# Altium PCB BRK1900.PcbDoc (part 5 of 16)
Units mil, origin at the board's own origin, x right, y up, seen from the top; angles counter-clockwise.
Board outline 8858.27 x 5905.51 mil, 10 copper layers (L1-TOP, L2-GND, L3-PWR, L4-GND, L5-PWR, L6-PWR, L7-GND, L8-SIG, L9-GND, L10-BOT), stack 48.824 mil thick; 456 components, 571 nets, 2296 pads, 2416 vias.
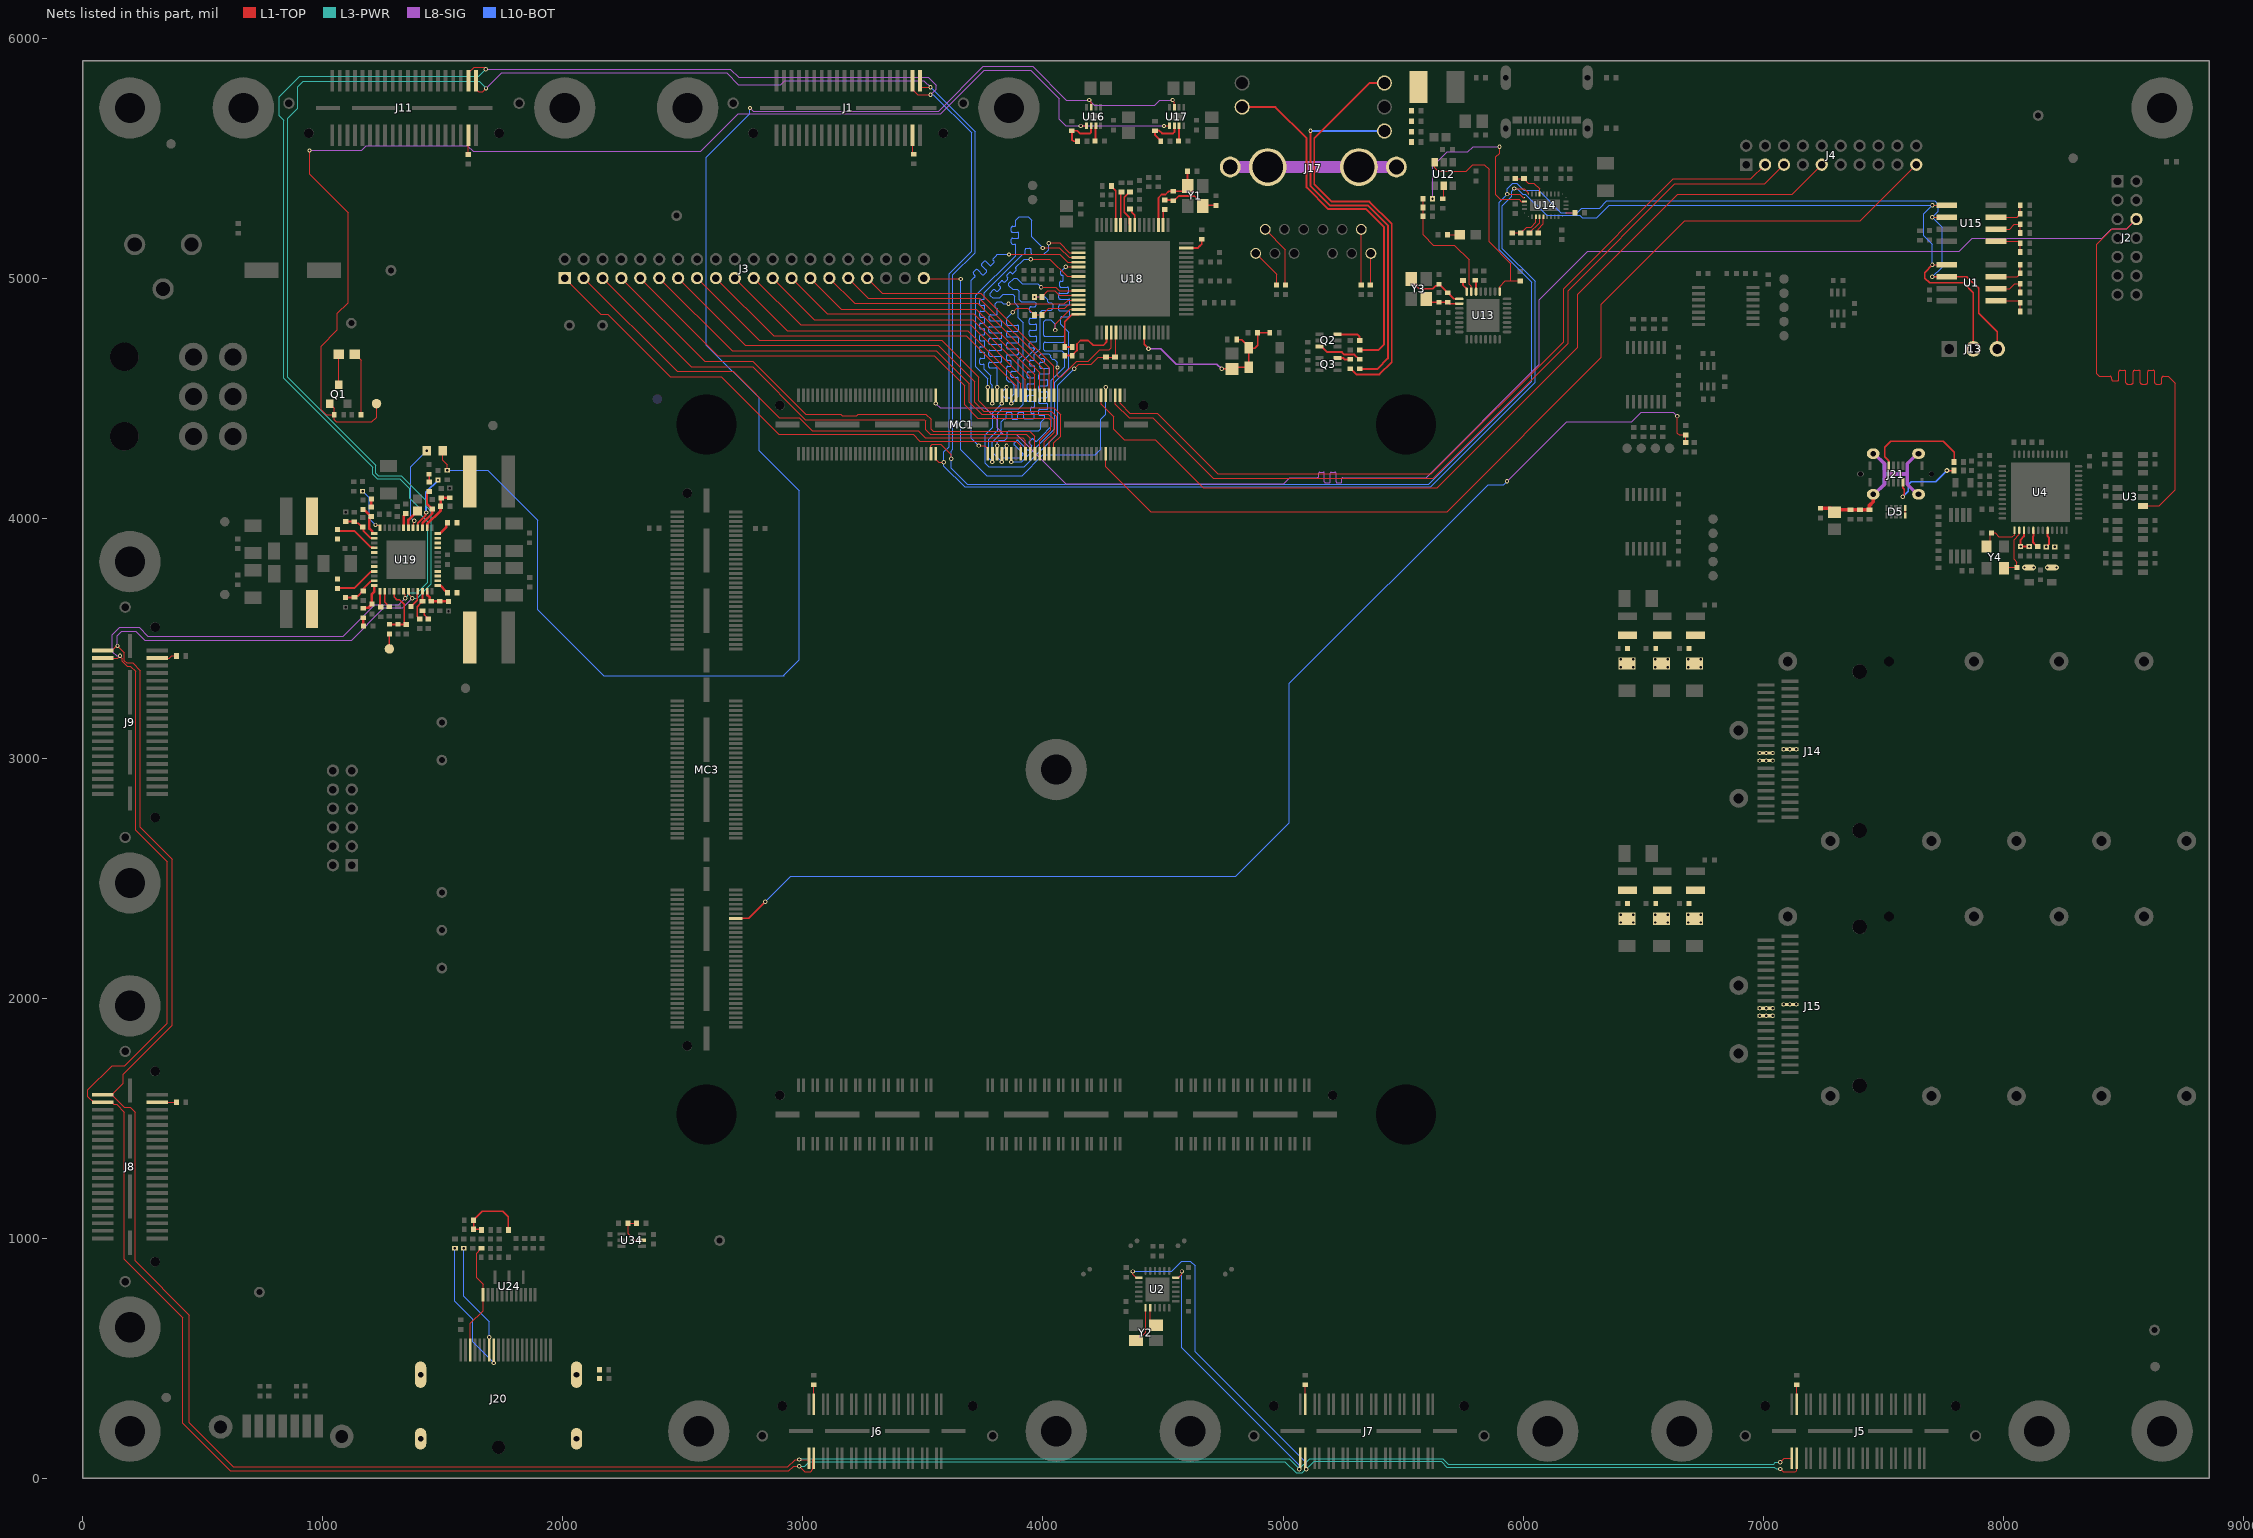
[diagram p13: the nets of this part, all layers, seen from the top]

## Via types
v1: diameter 18, hole 10, L1-TOP to L10-BOT, tented both sides, 2170 vias
v2: diameter 20, hole 10, L1-TOP to L10-BOT, tented both sides, 246 vias

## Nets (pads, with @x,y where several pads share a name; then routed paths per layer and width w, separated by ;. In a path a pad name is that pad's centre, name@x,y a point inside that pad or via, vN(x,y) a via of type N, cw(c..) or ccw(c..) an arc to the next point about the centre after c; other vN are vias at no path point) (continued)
GIGE_RX_CLK: MC1.64 U18.43 | length 1477.6
  L1-TOP w4.55: v1(3992.13,4962.11) 4053.64,4962.11 4067.68,4948.07 U18.43@4148.24,4948.07
  L10-BOT w4.55: v1(3789.37,4234.11) 3774,4249.48 3774,4329 3811.02,4366.02 3811.02,4437.01 3830.29,4456.27 3899.35,4456.27 3917.32,4474.24 3917.32,4655.08 3959.65,4697.4 3963.36,4701.11 ccw(c3959.89,4704.58) 3959.89,4709.49 3947.71,4709.49 cw(c3947.71,4714.4) 3942.8,4714.4 3942.8,4729.14 cw(c3947.71,4729.14) 3947.71,4734.05 3968.8,4734.05 ccw(c3968.8,4738.95) 3973.71,4738.95 3973.71,4753.68 ccw(c3968.8,4753.68) 3968.8,4758.59 3947.71,4758.59 cw(c3947.71,4763.5) 3942.8,4763.5 3942.8,4778.23 cw(c3947.71,4778.23) 3947.71,4783.14 3968.8,4783.14 ccw(c3968.8,4788.06) 3973.71,4788.06 3973.71,4802.78 ccw(c3968.8,4802.78) 3968.8,4807.69 3947.71,4807.69 cw(c3947.71,4812.6) 3942.8,4812.6 3942.8,4827.33 cw(c3947.71,4827.33) 3947.71,4832.24 3968.8,4832.24 ccw(c3968.8,4837.15) 3973.71,4837.15 3973.71,4851.89 ccw(c3968.8,4851.89) 3968.8,4856.8 3950.37,4856.8 cw(c3950.37,4861.7) 3945.46,4861.7 3945.46,4876.43 cw(c3950.37,4876.43) 3950.37,4881.34 3966.09,4881.34 ccw(c3966.09,4886.25) 3971,4886.25 3971,4895.14 3968.9,4897.24 3964.57,4901.57 3908.8,4901.57 3900.98,4909.39 3900.98,4944.8 3893.03,4952.76 3874.02,4952.76 3858.27,4968.5 3858.27,4978.52 3879.75,5000 3889.76,5000 3913.39,4976.38 3977.85,4976.38 v1(3992.13,4962.11)
GIGE_RX_DV: MC1.67 R95.1 R96.2 U18.53 | length 1234
  L1-TOP w4.55: v1(4129.92,4622.05) 4149.61,4641.73 4200.79,4641.73 4230.26,4671.21 R96.2@4262.72,4671.21 4262.95,4670.97 R95.1@4299.83,4670.97 4303.75,4674.89 U18.53@4303.75,4772.87
  L10-BOT w4.55: v1(3828.74,4477.42) 3791.34,4440.02 3791.34,4377.95 3759.84,4346.46 3759.84,4228.35 3774,4214.19 3922.85,4214.19 4060.73,4352.07 4060.73,4552.86 v1(4129.92,4622.05)
GIGE_RXD0: MC1.68 R62.1 R90.2 U18.44 | length 1492.4
  L1-TOP w4.55: R62.1@3964.57,4923.23 v1(3964.57,4921.26) R90.2@3996.06,4921.26 3996.06,4923.23 4019.33,4946.49 4049.57,4946.49 4067.68,4928.38 U18.44@4148.24,4928.38
  L10-BOT w4.55: v1(3828.74,4234.11) 3787.88,4274.97 3787.88,4315.88 3826.55,4354.55 3826.55,4401.35 3838.58,4413.39 3839.28,4413.39 3841.56,4413.39 ccw(c3841.56,4418.3) 3846.47,4418.3 3846.47,4435.65 cw(c3851.38,4435.65) 3851.38,4440.56 3866.11,4440.56 cw(c3866.11,4435.65) 3871.02,4435.65 3871.02,4416.88 ccw(c3875.93,4416.88) 3875.93,4411.97 3890.66,4411.97 ccw(c3890.66,4416.88) 3895.57,4416.88 3895.57,4435.65 cw(c3900.48,4435.65) 3900.48,4440.56 3915.21,4440.56 cw(c3915.21,4435.65) 3920.12,4435.65 3920.12,4418.3 ccw(c3925.03,4418.3) 3925.03,4413.39 3952.76,4413.39 3958.85,4413.39 3964.6,4419.13 3964.6,4430.37 3964.6,4432.65 ccw(c3959.69,4432.65) 3959.69,4437.56 3953.11,4437.56 cw(c3953.11,4442.47) 3948.2,4442.47 3948.2,4457.2 cw(c3953.11,4457.2) 3953.11,4462.11 3961.19,4462.11 ccw(c3961.19,4467.02) 3966.1,4467.02 3966.1,4481.75 ccw(c3961.19,4481.75) 3961.19,4486.66 3939.37,4486.66 cw(c3939.37,4491.57) 3934.46,4491.57 3934.46,4506.3 cw(c3939.37,4506.3) 3939.37,4511.21 3961.19,4511.21 ccw(c3961.19,4516.12) 3966.1,4516.12 3966.1,4530.85 ccw(c3961.19,4530.85) 3961.19,4535.76 3939.37,4535.76 cw(c3939.37,4540.67) 3934.46,4540.67 3934.46,4555.4 cw(c3939.37,4555.4) 3939.37,4560.31 3961.19,4560.31 ccw(c3961.19,4565.22) 3966.1,4565.22 3966.1,4579.95 ccw(c3961.19,4579.95) 3961.19,4584.86 3939.37,4584.86 cw(c3939.37,4589.77) 3934.46,4589.77 3934.46,4604.5 cw(c3939.37,4604.5) 3939.37,4609.41 3961.19,4609.41 ccw(c3961.19,4614.32) 3966.1,4614.32 3966.1,4629.05 ccw(c3961.19,4629.05) 3961.19,4633.96 3948.87,4633.96 cw(c3948.87,4638.87) 3943.96,4638.87 3943.96,4653.6 cw(c3948.87,4653.6) 3948.87,4658.51 3959.69,4658.51 ccw(c3959.69,4663.42) 3964.6,4663.42 3964.6,4677.17 3964.6,4681.84 3988.19,4705.43 3988.19,4858.27 3996.06,4866.14 4035.43,4866.14 4043.31,4874.02 4043.31,4889.76 4035.43,4897.64 4023.62,4897.64 4019.69,4901.57 4019.69,4909.45 4007.87,4921.26 v1(3964.57,4921.26)
GIGE_RXD1: MC1.65 U18.45 | length 1171
  L1-TOP w4.55: v1(3856.47,4892.79) 4089.49,4892.79 4105.39,4908.7 U18.45@4148.24,4908.7
  L10-BOT w4.55: v1(3809.05,4545.42) 3809.05,4618.7 3809.05,4620.98 ccw(c3804.14,4620.98) 3804.14,4625.89 3779.32,4625.89 cw(c3779.32,4630.8) 3774.41,4630.8 3774.41,4645.53 cw(c3779.32,4645.53) 3779.32,4650.44 3824.22,4650.44 ccw(c3824.22,4655.35) 3829.13,4655.35 3829.13,4670.08 ccw(c3824.22,4670.08) 3824.22,4674.99 3779.32,4674.99 cw(c3779.32,4679.9) 3774.41,4679.9 3774.41,4694.63 cw(c3779.32,4694.63) 3779.32,4699.54 3824.22,4699.54 ccw(c3824.22,4704.45) 3829.13,4704.45 3829.13,4719.18 ccw(c3824.22,4719.18) 3824.22,4724.09 3779.32,4724.09 cw(c3779.32,4729) 3774.41,4729 3774.41,4743.73 cw(c3779.32,4743.73) 3779.32,4748.64 3824.22,4748.64 ccw(c3824.22,4753.55) 3829.13,4753.55 3829.13,4768.28 ccw(c3824.22,4768.28) 3824.22,4773.19 3779.32,4773.19 cw(c3779.32,4778.1) 3774.41,4778.1 3774.41,4792.83 cw(c3779.32,4792.83) 3779.32,4797.74 3824.22,4797.74 ccw(c3824.22,4802.65) 3829.13,4802.65 3829.13,4817.38 ccw(c3824.22,4817.38) 3824.22,4822.29 3781.98,4822.29 cw(c3781.98,4827.2) 3777.07,4827.2 3777.07,4841.93 cw(c3781.98,4841.93) 3781.98,4846.84 3804.14,4846.84 ccw(c3804.14,4851.75) 3809.05,4851.75 3809.05,4869.7 3809.05,4871.83 3801.59,4879.3 3801.59,4893.51 3809.65,4901.57 3826.77,4901.57 3835.56,4892.79 v1(3856.47,4892.79)
GIGE_RXD2: MC1.69 R63.1 R91.2 U18.46 | length 1087.6
  L1-TOP w4.55: v1(3874.02,4858.27) 3889.76,4874.02 3937.01,4874.02 3955.03,4855.99 3957,4855.99 3964.57,4848.43 R63.1@3964.57,4846.46 R91.2@3996.06,4846.46 4023.62,4874.02 4090.55,4874.02 4104.89,4888.35 4147.58,4888.35 U18.46@4148.24,4889.01
  L10-BOT w4.55: v1(3848.42,4545.42) 3832,4528.99 3832,4510 3840,4502 3865,4502 3881,4518 3881,4554 3867.12,4567.88 3857.77,4567.88 3848.42,4577.23 3848.42,4582.68 3848.42,4627.25 cw(c3853.33,4627.25) 3853.33,4632.16 3862.13,4632.16 ccw(c3862.13,4637.07) 3867.04,4637.07 3867.04,4651.8 ccw(c3862.13,4651.8) 3862.13,4656.71 3852.97,4656.71 cw(c3852.97,4661.62) 3848.06,4661.62 3848.06,4676.35 cw(c3852.97,4676.35) 3852.97,4681.26 3893.51,4681.26 ccw(c3893.51,4686.17) 3898.42,4686.17 3898.42,4700.9 ccw(c3893.51,4700.9) 3893.51,4705.81 3852.97,4705.81 cw(c3852.97,4710.72) 3848.06,4710.72 3848.06,4725.45 cw(c3852.97,4725.45) 3852.97,4730.36 3893.51,4730.36 ccw(c3893.51,4735.27) 3898.42,4735.27 3898.42,4750 ccw(c3893.51,4750) 3893.51,4754.91 3852.97,4754.91 cw(c3852.97,4759.82) 3848.06,4759.82 3848.06,4774.55 cw(c3852.97,4774.55) 3852.97,4779.46 3893.51,4779.46 ccw(c3893.51,4784.37) 3898.42,4784.37 3898.42,4799.1 ccw(c3893.51,4799.1) 3893.51,4804.01 3853.33,4804.01 cw(c3853.33,4808.92) 3848.42,4808.92 3848.42,4811.2 3848.42,4832.68 v1(3874.02,4858.27)
GIGE_RXD3: MC1.70 U18.47 | length 1401.9
  L1-TOP w4.55: v1(4051.18,4783.46) 4051.18,4807.09 4113.42,4869.33 U18.47@4148.24,4869.33
  L10-BOT w4.55: v1(3848.42,4302.11) 3826.77,4280.46 3826.77,4259.84 3834.65,4251.97 3905.51,4251.97 3909.45,4255.91 3916.1,4262.56 ccw(c3912.63,4266.03) 3916.1,4269.5 3879.58,4306.02 cw(c3883.06,4309.5) 3879.58,4312.97 3890,4323.38 cw(c3893.47,4319.91) 3896.94,4323.38 3935.12,4285.21 ccw(c3938.59,4288.68) 3942.06,4285.21 3952.48,4295.62 ccw(c3949.01,4299.09) 3952.48,4302.57 3943.07,4311.98 cw(c3946.54,4315.45) 3943.07,4318.92 3953.49,4329.34 cw(c3956.96,4325.86) 3960.43,4329.34 3968.18,4321.58 ccw(c3971.65,4325.05) 3975.13,4321.58 3994.09,4340.55 4035.43,4381.89 4035.43,4574.8 4090.55,4629.92 4090.55,4685.04 4078.74,4696.85 4008.37,4696.85 4004.08,4701.14 4003.94,4701.28 4003.94,4727.97 cw(c4008.85,4727.97) 4008.85,4732.88 4086.71,4732.88 ccw(c4086.71,4737.79) 4091.62,4737.79 4091.62,4752.52 ccw(c4086.71,4752.52) 4086.71,4757.43 4008.85,4757.43 cw(c4008.85,4762.34) 4003.94,4762.34 4003.94,4799.21 4003.94,4818.9 4011.81,4826.77 4031.5,4826.77 4051.18,4807.09 v1(4051.18,4783.46)
GIGE_RXD4: R64.1 R92.2 U18.48 | length 208.2
  L1-TOP w7.5: R92.2@4122.05,4712.6 R64.1@4090.55,4712.6 4090.55,4818.9 4119.14,4847.49 4146.08,4847.49 U18.48@4148.24,4849.64
GIGE_RXD7: R104.1 R105.2 U18.51 | length 272
  L1-TOP w7.5: R104.1@4090.55,4677.17 R105.2@4122.05,4677.17 ; R105.2@4122.05,4675.2 R105.2@4122.05,4677.17 ; U18.51@4264.38,4772.87 4264.38,4732.88 4251.97,4720.47 4208.66,4720.47 4188.98,4740.16 4156.36,4740.16 4141.73,4725.53 4141.73,4698.82 4122.05,4679.13 R105.2@4122.05,4677.17
GIGE_TX_CLK: MC1.71 U18.40 | length 1180.5
  L1-TOP w4.55: v1(3948.82,5078.74) 4029.07,5078.74 4100.69,5007.12 U18.40@4148.24,5007.12
  L10-BOT w4.55: v1(3868.11,4477.42) 3897.64,4506.95 3897.64,4579.97 3897.64,4582.24 ccw(c3892.73,4582.24) 3892.73,4587.15 3871.53,4587.15 cw(c3871.53,4592.06) 3866.62,4592.06 3866.62,4606.79 cw(c3871.53,4606.79) 3871.53,4611.7 3892.73,4611.7 ccw(c3892.73,4616.61) 3897.64,4616.61 3897.64,4653.54 3897.64,4661.42 3917.32,4681.1 3917.32,4814.96 3898,4834.28 3898,4881.53 3882.16,4897.37 3882.16,4924.91 3874,4933.07 3834.95,4933.07 3819.2,4917.32 3789.82,4917.32 3780,4927.14 3780,4929.39 3780,4937.48 3793.19,4950.67 cw(c3796.66,4947.2) 3800.13,4950.67 3805.02,4945.78 ccw(c3808.49,4949.26) 3811.97,4945.78 3822.38,4956.2 ccw(c3818.91,4959.67) 3822.38,4963.14 3815.17,4970.36 cw(c3818.64,4973.83) 3815.17,4977.3 3825.58,4987.72 cw(c3829.05,4984.25) 3832.53,4987.72 3835.18,4985.06 ccw(c3838.65,4988.54) 3842.12,4985.06 3852.54,4995.48 ccw(c3849.07,4998.95) 3852.54,5002.42 3849.89,5005.08 cw(c3853.36,5008.55) 3849.89,5012.02 3860.3,5022.44 cw(c3863.77,5018.97) 3867.24,5022.44 3869.57,5020.11 ccw(c3873.05,5023.58) 3876.52,5020.11 3886.93,5030.52 ccw(c3883.46,5034) 3886.93,5037.47 cw(c3890.4,5040.94) 3886.93,5044.41 3917.32,5074.8 3921.26,5078.74 v1(3948.82,5078.74)
GIGE_TX_EN: MC1.66 U18.52 | length 1372.2
  L1-TOP w4.55: v1(4060.6,4627.48) 4059.06,4625.94 4059.06,4594.52 4064.39,4589.19 4075.46,4589.19 4140.53,4654.26 4189.14,4654.26 4235.67,4700.79 4276.05,4700.79 4284.06,4708.8 U18.52@4284.06,4772.87
  L10-BOT w4.55: v1(3809.05,4302.11) 3809.05,4316.93 3817.63,4325.5 3841.55,4325.5 3850.92,4334.87 3850.92,4358.79 3856.86,4364.73 3981.86,4364.73 3990,4372.87 3990,4399 4007.87,4416.87 4007.87,4421.61 4007.87,4423.89 ccw(c4002.96,4423.89) 4002.96,4428.8 3987.16,4428.8 cw(c3987.16,4433.71) 3982.25,4433.71 3982.25,4448.44 cw(c3987.16,4448.44) 3987.16,4453.35 4014.6,4453.35 ccw(c4014.6,4458.26) 4019.51,4458.26 4019.51,4472.99 ccw(c4014.6,4472.99) 4014.6,4477.9 3987.16,4477.9 cw(c3987.16,4482.81) 3982.25,4482.81 3982.25,4497.54 cw(c3987.16,4497.54) 3987.16,4502.45 4014.6,4502.45 ccw(c4014.6,4507.36) 4019.51,4507.36 4019.51,4522.09 ccw(c4014.6,4522.09) 4014.6,4527 3987.16,4527 cw(c3987.16,4531.91) 3982.25,4531.91 3982.25,4546.64 cw(c3987.16,4546.64) 3987.16,4551.55 4014.6,4551.55 ccw(c4014.6,4556.46) 4019.51,4556.46 4019.51,4571.19 ccw(c4014.6,4571.19) 4014.6,4576.1 3987.16,4576.1 cw(c3987.16,4581.01) 3982.25,4581.01 3982.25,4595.74 cw(c3987.16,4595.74) 3987.16,4600.65 4022.96,4600.65 ccw(c4022.96,4605.56) 4027.87,4605.56 4027.87,4620.29 ccw(c4022.96,4620.29) 4022.96,4625.2 3990.97,4625.2 cw(c3990.97,4630.11) 3986.06,4630.11 3986.06,4644.84 cw(c3990.97,4644.84) 3990.97,4649.75 4002.96,4649.75 ccw(c4002.96,4654.66) 4007.87,4654.66 4007.87,4659.39 4002.09,4665.17 4000.18,4667.08 3988.37,4667.08 3984.25,4671.2 3984.25,4677.17 3992.13,4685.04 4023.62,4685.04 4031.5,4677.17 4031.5,4669.29 4039.37,4661.42 4047.24,4661.42 4058.83,4649.83 4058.83,4629.26 v1(4060.6,4627.48)
GIGE_TXD0: MC1.72 U18.38 | length 1260.6
  L1-TOP w4.55: v1(4094.49,5047.24) 4094.86,5046.87 4147.86,5046.87 U18.38@4148.24,5046.49
  L10-BOT w4.55: v1(3868.11,4234.11) 3911.28,4234.11 4049.01,4371.84 4049.01,4565.84 4108.28,4625.11 4108.28,4773.61 4074.8,4807.09 4074.8,4807.5 4074.8,4834.32 cw(c4079.71,4834.32) 4079.71,4839.23 4106.88,4839.23 ccw(c4106.88,4844.14) 4111.79,4844.14 4111.79,4858.87 ccw(c4106.88,4858.87) 4106.88,4863.78 4069.93,4863.78 cw(c4069.93,4868.69) 4065.02,4868.69 4065.02,4883.42 cw(c4069.93,4883.42) 4069.93,4888.33 4106.88,4888.33 ccw(c4106.88,4893.24) 4111.79,4893.24 4111.79,4907.97 ccw(c4106.88,4907.97) 4106.88,4912.88 4069.93,4912.88 cw(c4069.93,4917.79) 4065.02,4917.79 4065.02,4932.52 cw(c4069.93,4932.52) 4069.93,4937.43 4101.79,4937.43 ccw(c4101.79,4942.34) 4106.7,4942.34 4106.7,4957.07 ccw(c4101.79,4957.07) 4101.79,4961.98 4074.8,4961.98 cw(c4074.8,4966.89) 4069.89,4966.89 4069.89,4981.62 cw(c4074.8,4981.62) 4074.8,4986.53 4079.71,4986.53 ccw(c4079.71,4991.44) 4084.62,4991.44 4084.62,5006.17 ccw(c4079.71,5006.17) 4079.71,5011.08 cw(c4079.71,5015.99) 4074.8,5015.99 4074.8,5027.56 4082.98,5035.74 v1(4094.49,5047.24)
GIGE_TXD1: MC1.62 U18.37 | length 1386.4
  L1-TOP w4.55: v1(3733.02,4302.37) 3756.63,4302.37 3769.68,4289.32 MC1.62@3769.68,4268.11 ; v1(3858.27,5098.43) 4070.87,5098.43 4103.12,5066.18 U18.37@4148.24,5066.18
  L10-BOT w4.55: v1(3733.02,4302.37) 3702,4333.38 3702,4990.1 3714.41,5002.51 3716.02,5004.12 ccw(c3712.55,5007.59) 3716.02,5011.06 3710.02,5017.06 cw(c3713.49,5020.53) 3710.02,5024 3720.44,5034.42 cw(c3723.91,5030.95) 3727.38,5034.42 3746.94,5014.86 ccw(c3750.41,5018.33) 3753.89,5014.86 3764.3,5025.27 ccw(c3760.83,5028.75) 3764.3,5032.22 3744.74,5051.78 cw(c3748.21,5055.25) 3744.74,5058.72 3755.16,5069.14 cw(c3758.63,5065.67) 3762.1,5069.14 3777.86,5053.38 ccw(c3781.33,5056.85) 3784.8,5053.38 3795.22,5063.79 ccw(c3791.75,5067.27) 3795.22,5070.74 3792.4,5073.56 cw(c3795.87,5077.03) 3792.4,5080.5 3805.58,5093.68 3810.32,5098.43 v1(3858.27,5098.43)
GIGE_TXD2: MC1.61 U18.36 | length 1244.8
  L1-TOP w4.55: v1(3998.51,5125.51) 4068.83,5125.51 4108.48,5085.86 U18.36@4148.24,5085.86
  L10-BOT w4.55: v1(3769.68,4545.42) 3769.68,4580.71 3720.47,4629.92 3720.47,4927.83 3886.48,5093.84 3886.48,5134.11 3886.48,5136.39 ccw(c3881.57,5136.39) 3881.57,5141.3 3873.49,5141.3 cw(c3873.49,5146.21) 3868.58,5146.21 3868.58,5160.94 cw(c3873.49,5160.94) 3873.49,5165.85 3894.56,5165.85 ccw(c3894.56,5170.76) 3899.47,5170.76 3899.47,5185.49 ccw(c3894.56,5185.49) 3894.56,5190.4 3873.49,5190.4 cw(c3873.49,5195.31) 3868.58,5195.31 3868.58,5210.04 cw(c3873.49,5210.04) 3873.49,5214.95 3881.57,5214.95 ccw(c3881.57,5219.86) 3886.48,5219.86 3886.48,5228.35 3886.48,5241.11 3901.1,5255.73 3938.46,5255.73 3952.76,5241.43 3952.76,5171.27 v1(3998.51,5125.51)
GIGE_TXD3: MC1.63 U18.35 | length 1240.2
  L1-TOP w4.55: v1(4024.53,5145.1) 4026.36,5146.94 4069.6,5146.94 4110.47,5106.06 4147.72,5106.06 U18.35@4148.24,5105.55
  L10-BOT w4.55: v1(3789.37,4477.42) 3789.37,4553.15 3783.46,4559.06 3783.46,4592.46 3755.91,4620.01 3755.91,4633.86 3755.91,4636.14 ccw(c3751,4636.14) 3751,4641.05 3740.82,4641.05 cw(c3740.82,4645.96) 3735.91,4645.96 3735.91,4660.69 cw(c3740.82,4660.69) 3740.82,4665.6 3753.36,4665.6 ccw(c3753.36,4670.51) 3758.27,4670.51 3758.27,4685.24 ccw(c3753.36,4685.24) 3753.36,4690.15 3740.82,4690.15 cw(c3740.82,4695.06) 3735.91,4695.06 3735.91,4709.79 cw(c3740.82,4709.79) 3740.82,4714.7 3753.36,4714.7 ccw(c3753.36,4719.61) 3758.27,4719.61 3758.27,4734.34 ccw(c3753.36,4734.34) 3753.36,4739.25 3740.82,4739.25 cw(c3740.82,4744.16) 3735.91,4744.16 3735.91,4758.89 cw(c3740.82,4758.89) 3740.82,4763.8 3753.36,4763.8 ccw(c3753.36,4768.71) 3758.27,4768.71 3758.27,4783.44 ccw(c3753.36,4783.44) 3753.36,4788.35 3740.82,4788.35 cw(c3740.82,4793.26) 3735.91,4793.26 3735.91,4807.99 cw(c3740.82,4807.99) 3740.82,4812.9 3753.36,4812.9 ccw(c3753.36,4817.81) 3758.27,4817.81 3758.27,4832.54 ccw(c3753.36,4832.54) 3753.36,4837.45 3740.82,4837.45 cw(c3740.82,4842.36) 3735.91,4842.36 3735.91,4857.09 cw(c3740.82,4857.09) 3740.82,4862 3753.36,4862 ccw(c3753.36,4866.91) 3758.27,4866.91 3758.27,4881.64 ccw(c3753.36,4881.64) 3753.36,4886.55 3740.82,4886.55 cw(c3740.82,4891.46) 3735.91,4891.46 3735.91,4906.19 cw(c3740.82,4906.19) 3740.82,4911.1 3751,4911.1 ccw(c3751,4916.01) 3755.91,4916.01 3755.91,4933.23 3755.91,4938.15 3916.18,5098.43 3918.46,5098.43 3920.73,5098.43 ccw(c3920.73,5103.34) 3925.64,5103.34 3925.64,5118.34 cw(c3930.55,5118.34) 3930.55,5123.25 3945.28,5123.25 cw(c3945.28,5118.34) 3950.19,5118.34 3950.19,5103.34 ccw(c3955.1,5103.34) 3955.1,5098.43 3996.12,5098.43 4003.94,5098.43 4024.53,5119.01 v1(4024.53,5145.1)
LED_1000_LINK: Q2.3 R102.2 | length 189.3
  L1-TOP w8: Q2.3@5151.57,4714.57 5160.43,4714.57 5183.26,4691.74 5245.27,4691.74 5255.91,4681.1 5297.24,4681.1 5316.93,4661.42 R102.2@5318.9,4661.42
LED_ACT: Q2.6 R94.2 | length 112.3
  L1-TOP w8: Q2.6@5226.38,4765.75 5309.05,4765.75 5318.9,4755.91 R94.2@5318.9,4740.16
LED_LINK: Q3.6 R98.2 | length 55.6
  L1-TOP w8: Q3.6@5226.38,4667.32 5250,4667.32 5255.91,4661.42 R98.2@5279.53,4661.42
NetC9_2: C9.2 C10.2 FB2.2 U4.8 | length 76.8
  L1-TOP w8: v2(8178.76,3880.33) 8179.35,3880.33 8185.58,3886.57 8185.58,3887.16 8190.57,3892.14 8190.57,3918.91 8184.66,3924.82 U4.8@8184.66,3949.42
  other v2: 8183.09,3794.5 8221.67,3794.5 8214.19,3880.33
NetC13_2: C13.2 C14.2 FB3.2 U4.3 | length 108.8
  L1-TOP w7: v2(8072.46,3881.9) 8072.65,3882.1 v2(8107.69,3882.1) C14.2@8107.89,3882.3
  L1-TOP w8: v2(8072.46,3881.9) 8072.46,3910.2 8086.24,3923.98 U4.3@8086.24,3949.42
  other v2: 8088.6,3794.5 8127.18,3794.5
NetC36_2: C36.2 FB5.1 J21.M1 J21.M2 J21.M3 J21.M4 R22.1 R23.1 R24.1 | length 808.3
  L1-TOP w15: C36.2@7238.57,4041.35 7256.89,4041.35 7281.5,4041.33 FB5.1@7297.62,4025.21 7307.47,4035.05 R22.1@7363.79,4035.05 R23.1@7403.16,4035.05 R24.1@7442.53,4035.05 7442.53,4052.77 7458.28,4068.52 J21.M2@7458.28,4099.23
  L8-SIG w15: J21.M2@7458.28,4099.23 7463.2,4099.23 7505.53,4141.55 7505.53,4183.87 ; J21.M3@7458.28,4268.52 7463.2,4268.52 7505.53,4226.2 7505.53,4183.87 ; J21.M1@7647.26,4099.23 7642.34,4099.23 7600.02,4141.55 7600.02,4183.87 ; J21.M4@7647.26,4268.52 7642.34,4268.52 7600.02,4226.2 7600.02,4183.87 ; 7505.53,4183.87 7600.02,4183.87
NetC37_2: C37.2 U4.1 Y4.1 | length 189.8
  L1-TOP w4.96: Y4.1@7929.74,3881.51 7945.48,3897.25 7945.48,3933.27 C37.2@7950.8,3938.6 7966.16,3938.6 7981.9,3922.85 8038.11,3922.85 8046.87,3931.6 U4.1@8046.87,3949.42
NetC38_2: C38.2 U4.2 Y4.3 | length 223.9
  L1-TOP w4.96: Y4.3@8002.57,3790.96 8006.9,3795.29 C38.2@8056.71,3795.29 8056.71,3816.55 8044.9,3828.36 8044.9,3911.04 8066.55,3932.69 U4.2@8066.55,3949.42
NetC53_2: C53.2 C54.2 J14.30 L5.2
  other v1: 6986.15,2990.26 7012.61,2990.26 7039.08,2990.26 6549.79,3378.6 6601.79,3378.6 6549.79,3411.52 6601.79,3411.52
NetC55_2: C55.2 C56.2 J14.29 L6.2
  other v1: 6986.15,3021.76 7012.61,3021.76 7039.08,3021.76 6688.57,3378.6 6740.57,3378.6 6688.57,3411.52 6740.57,3411.52
NetC57_2: C57.2 C58.2 J14.10 L7.2
  other v1: 7084.97,3037.5 7111.43,3037.5 7137.9,3037.5 6407.07,3378.6 6459.07,3378.6 6407.07,3411.52 6459.07,3411.52
NetC77_2: C77.2 R75.2 U13.26 Y3.1 | length 145.6
  L1-TOP w7: Y3.1@5597.02,4913.28 5611.09,4899.2 C77.2@5650.02,4899.2 5650.41,4899.59 R75.2@5686.02,4899.59 5691.93,4893.68 U13.26@5734.14,4893.68
NetC78_2: C78.2 R75.1 U13.25 Y3.3 | length 257.6
  L1-TOP w7: Y3.3@5534.02,4996.74 5554.15,4976.62 5554.15,4968.15 5567.02,4955.28 5624.02,4955.28 5636.2,4967.46 5642.69,4967.46 5649.43,4974.2 C78.2@5650.02,4974.2 5656.75,4967.46 5657.52,4967.46 5677.7,4947.27 5677.7,4945.3 5684.05,4938.96 R75.1@5686.02,4938.96 5687.98,4938.96 5694.33,4932.62 5694.33,4930.65 5711.61,4913.36 U13.25@5734.14,4913.36
NetC83_1: C83.1 U16.7 | length 64.4
  L1-TOP w8: C83.1@4218.11,5570.47 4219.29,5571.65 4219.29,5632.68 U16.7@4220.47,5633.86
NetC87_1: C87.1 U17.7 | length 64.4
  L1-TOP w8: C87.1@4564.57,5570.47 4565.75,5571.65 4565.75,5632.68 U17.7@4566.93,5633.86
NetC111_2: C111.2 J17.12 | length 132.8
  L1-TOP w5: C111.2@5363,4971.08 5366,4974.08 J17.12@5366,5102.6
NetC112_2: C112.2 J17.6 | length 231.5
  L1-TOP w5: C112.2@5326,4971.08 J17.6@5326,5202.6
NetC113_2: C113.2 U19.18 | length 86.4
  L1-TOP w11: U19.18@1356.43,3959.53 1356.43,3992.83 C113.2@1394,4030.39
NetC114_2: C114.2 U19.19 | length 64.8
  L1-TOP w11: U19.19@1337.15,3959.93 U19.19@1336.74,3959.53 1336.74,4008.38 1340.67,4012.3 1340.67,4014.82 1345.4,4019.56 C114.2@1345.99,4019.56
NetC118_1: C118.1 U19.1 | length 53.7
  L1-TOP w11: U19.1@1478.47,3719.37 1478.88,3718.96 1490.18,3718.96 1514.18,3694.96 1514.77,3694.96 1519.5,3690.23 C118.1@1519.5,3689.64
NetC118_2: C118.2 L1.1 U19.2 U19.3 U19.4
NetC122_1: C122.1 R122.1 R123.2 U19.47 | length 114.6
  L1-TOP w11: U19.47@1435.17,3695.75 1435.17,3680.9 1444.6,3671.47 1444.75,3671.47 1445.27,3670.95 R123.2@1445.27,3657.67 ; R123.2@1451.58,3653.32 1522.98,3653.32 C122.1@1523.58,3652.72
NetC123_1: C123.1 R124.2 | length 43.7
  L1-TOP w7: R124.2@1415.58,3613.95 1415.91,3613.95 1422.26,3607.61 1422.26,3598.12 C123.1@1432.33,3588.04 ; C123.1@1432.33,3582.45 C123.1@1432.33,3583.04 ; C123.1@1432.33,3587.45 1439.07,3580.72 C123.1@1439.66,3580.72
NetC124_1: C124.1 U19.45 | length 73.6
  L1-TOP w7: C124.1@1368.92,3633.27 1393.39,3657.74 1393.39,3693.34 U19.45@1395.8,3695.75
NetC125_1: C125.1 R124.1 U19.46 | length 134.9
  L1-TOP w7: C125.1@1403.58,3580.64 1402.99,3580.64 1396.26,3587.37 1396.26,3587.96 1393.58,3590.64 1393.58,3631.32 1407.27,3645.01 1407.27,3646.98 R124.1@1413.61,3653.32 ; R124.1@1413.61,3648.32 1415.58,3648.32 1415.48,3648.43 U19.46@1415.48,3695.75
NetC126_1: C126.1 U19.12 | length 67.2
  L1-TOP w11: U19.12@1478.47,3935.91 1478.88,3936.31 1488.26,3936.31 1514.84,3962.9 1514.84,3975.98 C126.1@1519.5,3980.64
NetC126_2: C126.2 L2.1 U19.9 U19.10 U19.11
NetC132_2: C132.2 U19.16 | length 234.3
  L1-TOP w8: U19.16@1395.8,3959.53 1395.8,3979.8 1428.53,4012.53 1428.53,4021.61 v1(1430.45,4023.52)
  L10-BOT w8: v1(1430.45,4023.52) 1430.45,4109.37 v1(1480,4158.92)
NetC133_1: C133.1 R125.1 R126.2 U19.14 | length 183.4
  L1-TOP w11: U19.14@1435.17,3959.53 1435.17,3974.83 1490.32,4029.98 R126.2@1490.32,4049 1492.16,4050.84 1492.16,4082.47 R125.1@1494,4084.31 1494.3,4084.62 1527.7,4084.62 C133.1@1528,4084.92
NetC136_1: C136.1 R127.2 | length 36.5
  L1-TOP w7: R127.2@1443,4146.38 C136.1@1443,4182.92
NetC137_1: C137.1 R127.1 U19.15 | length 181.8
  L1-TOP w10: U19.15@1415.48,3959.53 1415.48,3979.48 1456,4020 C137.1@1456,4037.92 1455.41,4037.92 1434,4059.33 1434,4102.31 R127.1@1443,4111.31
NetC138_1: C138.1 U19.24 | length 190.6
  L1-TOP w5: v1(1219.53,3971.72) 1220.78,3970.46 1234.91,3970.46 1238.32,3967.06 U19.24@1238.32,3959.53
  L10-BOT w5: v1(1166,4111.92) 1193,4084.92 1193,3998.24 v1(1219.53,3971.72)
NetC139_1: C139.1 U19.28 | length 182.1
  L1-TOP w8: C139.1@1061.58,3946.75 1131.02,3946.75 1199.01,3878.76 1212.79,3878.76 U19.28@1214.69,3876.85
NetC139_2: C139.2 L3.1 U19.29
NetC145_1: C145.1 R128.1 R130.2 U19.26 | length 155.5
  L1-TOP w8: C145.1@1090.8,3986.59 C145.1@1091.61,3985.79 ; C145.1@1095.8,3985.39 R128.1@1131.2,3985.39 1132,3984.59 1137.84,3978.75 1146.87,3978.75 1167.03,3958.59 1169,3958.59 1169,3946.88 1199.66,3916.22 U19.26@1214.69,3916.22
NetC146_1: C146.1 U19.37 | length 67.4
  L1-TOP w7: U19.37@1238.32,3695.75 1238.32,3632.58 C146.1@1241.29,3629.61
NetC147_1: C147.1 R129.2 | length 38.2
  L1-TOP w11: C147.1@1200.5,4083.64 1202.58,4081.56 R129.2@1202.58,4046.32
NetC148_1: C148.1 R129.1 U19.25 | length 135.4
  L1-TOP w11: C148.1@1167,4035.92 1171.74,4031.18 1176.38,4031.18 1200.61,4006.95 R129.1@1202.58,4006.95 1193.92,3998.29 1193.92,3956.68 1206.41,3944.19 1206.41,3936.31 1206.82,3935.91 U19.25@1214.69,3935.91
NetC149_1: C149.1 U19.33 | length 182.1
  L1-TOP w8: C149.1@1061.58,3708.53 1131.02,3708.53 1199.01,3776.52 1212.79,3776.52 U19.33@1214.69,3778.43
NetC149_2: C149.2 L4.1 U19.32
NetC153_1: C153.1 R132.1 R135.2 U19.35 | length 154.3
  L1-TOP w8: C153.1@1095,3669.08 1095.8,3669.88 1131.2,3669.88 R132.1@1132,3670.69 1137.84,3676.53 1146.87,3676.53 1167.03,3696.68 R135.2@1169,3696.68 1169,3706.26 1199.89,3737.15 1212.79,3737.15 U19.35@1214.69,3739.06
NetC154_1: C154.1 TP19.1 | length 62.6
  L1-TOP w7: TP19.1@1277.29,3455.53 1277.4,3455.64 C154.1@1277.4,3518.08
NetC154_2: C154.2 C156.2 R134.2 U19.40 | length 236.8
  L1-TOP w7: C154.2@1277.4,3558.24 1278.4,3557.24 1313.4,3557.24 R134.2@1346.43,3557.24 ; U19.40@1297.37,3695.75 1297.37,3671.45 1308.29,3660.53 1319.5,3660.53 1339.29,3640.73 1339.29,3566.35 1340.09,3565.55 1340.09,3563.58 R134.2@1346.43,3557.24 ; R134.2@1348.4,3557.24 R134.2@1346.43,3557.24
NetC155_1: C155.1 R133.2 | length 34.3
  L1-TOP w11: C155.1@1169.21,3550.53 1169.29,3550.61 R133.2@1169.29,3584.84
NetC157_1: C157.1 R133.1 U19.36 | length 124.7
  L1-TOP w11: R133.1@1169.29,3624.21 1171.89,3626.81 1189.68,3626.81 1199.26,3636.39 1199.26,3636.98 1203.99,3641.72 C157.1@1204.58,3641.72 1204.58,3683.64 1214.69,3693.75 U19.36@1214.69,3719.37
NetC159_2: C159.2 J17.1 | length 266.3
  L1-TOP w5: J17.1@4926,5202.6 5010,5118.6 C159.2@5010,4971.08
NetC163_2: C163.2 J17.7 | length 167.6
  L1-TOP w5: J17.7@4886,5102.6 4973,5015.6 C163.2@4973,4971.08
NetC164_2: C164.2 J17.S1 J17.S2 J17.T1 J17.T2 R107.2 R108.2 R109.2 R110.2 | length 692.1
  L8-SIG w50: J17.S2@4779.94,5462.6 J17.T2@4936.04,5462.6 J17.T1@5315.96,5462.6 J17.S1@5472.06,5462.6
NetC168_1: C168.1 R117.2 U18.19 Y1.1 | length 317.5
  L1-TOP w7: U18.19@4480.91,5221.69 4480.91,5335.24 4493.74,5348.07 4510.03,5348.07 4523.78,5361.81 R117.2@4543.31,5361.81 4582.24,5361.81 4602.36,5381.93 Y1.1@4602.36,5383.86 4601.97,5384.25 C168.1@4601.97,5444.88
NetC178_2: C178.2 C179.2 J15.30 L8.2
  other v1: 6986.14,1927.25 7012.61,1927.25 7039.07,1927.25 6549.79,2315.61 6601.79,2315.61 6549.79,2348.53 6601.79,2348.53
NetC180_2: C180.2 C181.2 J15.29 L9.2
  other v1: 6986.14,1958.75 7012.61,1958.75 7039.07,1958.75 6688.57,2315.61 6740.57,2315.61 6688.57,2348.53 6740.57,2348.53
NetC184_2: C184.2 C186.2 J15.10 L10.2
  other v1: 7084.96,1974.5 7111.43,1974.5 7137.89,1974.5 6407.07,2315.61 6459.07,2315.61 6407.07,2348.53 6459.07,2348.53
NetC190_2: C190.2 J20.SHELL1 J20.SHELL2 J20.SHELL3 J20.SHELL4 R155.2
NetC214_1: C214.1 R111.2 R117.1 Y1.3 | length 244.8
  L1-TOP w7: R111.2@4506.66,5325.01 4540.74,5325.01 R117.1@4543.31,5322.44 4545.28,5322.44 4564.96,5342.13 4629.53,5342.13 4665.35,5306.3 Y1.3@4665.35,5300.39 4667.72,5302.76 C214.1@4720.47,5302.76
NetC215_2: C215.2 D2.1 D3.1 R113.1 R119.2 R140.2 U18.59 | length 822.6
  L1-TOP w6: v1(4744.09,4622.05) 4786.42,4622.05 C215.2@4787.4,4621.06 4794.59,4628.25 D2.1@4856.64,4628.25 D3.1@4856.64,4709.25 ; R140.2@4807.09,4744.09 4827.9,4744.09 4856.64,4715.35 D3.1@4856.64,4709.25 ; R119.2@4944.88,4771.65 R113.1@4893.7,4771.65 4893.7,4720.47 4881.89,4708.66 4857.23,4708.66 D3.1@4856.64,4709.25
  L1-TOP w8: U18.59@4421.86,4772.87 4421.86,4723.66 v2(4439.58,4705.94)
  L8-SIG w6: v2(4439.58,4705.94) 4490.91,4705.94 4555.37,4641.48 4724.66,4641.48 v1(4744.09,4622.05)
NetD1_2: D1.2 R65.1 | length 51.9
  L1-TOP w5: R65.1@5684.69,5180 D1.2@5736.54,5180
NetD4_1: D4.1 Q1.3 | length 127.3
  L1-TOP w5: Q1.3@1065.7,4556.04 1065.7,4682.17 D4.1@1066.54,4683
NetD4_2: D4.2 R138.1 | length 262.9
  L1-TOP w5: D4.2@1133.46,4683 1159.69,4656.78 R138.1@1159.69,4431
NetD5_1,10: D5.1 D5.10 | length 30.5
  L1-TOP w5: D5.10@7592.14,4011.14 D5.1@7592.14,4041.65
NetJ1_4: J1.4 R1.2 | length 82.3
  L1-TOP w5: J1.4@3456.78,5595.86 3456.78,5520.91 R1.2@3462,5515.68
NetJ5_4: J5.4 R8.2 | length 80.9
  L1-TOP w5: J5.4@7139.32,309.84 7139.32,389.39 R8.2@7140.24,390.32
NetJ6_4: J6.4 R14.2 | length 80.5
  L1-TOP w5: J6.4@3044.83,309.84 3044.83,390.15 R14.2@3045,390.32
NetJ7_4: J7.4 R15.2 | length 80.9
  L1-TOP w5: J7.4@5092.08,309.84 5092.08,389.39 R15.2@5093,390.32
NetJ8_4: J8.4 R16.2 | length 80.7
  L1-TOP w4.55: J8.4@309.66,1567 R16.2@390.32,1567
NetJ9_4: J9.4 R17.2 | length 84.2
  L1-TOP w4.55: J9.4@309.65,3417.41 361.41,3417.41 370,3426 R17.2@390.31,3426
NetJ11_4: J11.4 R18.2 | length 81.3
  L1-TOP w4: R18.2@1606,5514.69 1606,5595.48 J11.4@1606.38,5595.86
NetJ17_13: J17.13 R94.1 | length 1518.7
  L1-TOP w8: J17.13@4829.94,5712.6 4968.5,5712.6 5098.43,5582.68 5098.43,5377.95 5188.98,5287.4 5346.46,5287.4 5421.26,5212.6 5421.26,4724.41 5397.64,4700.79 R94.1@5318.9,4700.79
NetJ17_15: J17.15 R102.1 | length 1619.4
  L1-TOP w8: v1(5114.17,5614.17) 5114.17,5384.48 5195.5,5303.15 5352.98,5303.15 5437.01,5219.12 5437.01,4665.35 5393.7,4622.05 R102.1@5318.9,4622.05
  L10-BOT w8: v1(5114.17,5614.17) 5114.96,5613.39 5421.28,5613.39 J17.15@5422.06,5612.6
NetJ17_17: J17.17 R98.1 | length 1750.6
  L1-TOP w8: R98.1@5279.53,4622.05 5281.5,4622.05 5305.12,4598.43 5401.57,4598.43 5452.76,4649.61 5452.76,5225.64 5359.5,5318.9 5202.02,5318.9 5129.92,5391 5129.92,5582.68 5359.84,5812.6 J17.17@5422.06,5812.6
NetJ20_13: J20.13 R156.1 | length 544.4
  L10-BOT w5: v1(1550.53,958.32) 1550.53,737 1624.53,663 1624.53,568.82 v1(1712.39,480.95)
NetJ20_14: J20.14 R157.1 | length 413.7
  L10-BOT w5: v1(1587.53,958.32) 1587.53,759 1693.12,653.41 v1(1693.12,588.34)
NetJ20_18: J20.18 R181.2 U24.1 | length 467
  L1-TOP w5: J20.18@1614.17,534.65 1614.17,645.67 1667.98,699.48 U24.1@1667.98,765 1667.98,808.54 1640.53,836 1640.53,939 1659.84,958.32 R181.2@1661.53,958.32
NetJ21_A5: J21.A5 R13.2 | length 342
  L1-TOP w6: v2(7580.97,4088.77) 7580.97,4092.1 7588.16,4099.28 7588.16,4121.11 7582.3,4126.98 J21.A5@7582.3,4149.82 ; v2(7765.37,4198.44) R13.2@7794.9,4198.44
  L10-BOT w6: v2(7580.97,4088.77) 7603.95,4111.74 7603.95,4139.39 7615.76,4151.2 7718.13,4151.2 v2(7765.37,4198.44)
NetJ21_B5: J21.B5 R19.1 | length 442.7
  L1-TOP w6: J21.B5@7523.24,4217.93 7523.24,4239.78 7507.25,4255.77 7507.25,4296.25 7531.49,4320.49 7749.62,4320.49 7794.9,4275.21 R19.1@7794.9,4233.87
NetMC3_48: MC3.48 R10.1 R11.2 | length 5282.7
  L1-TOP w5: v1(6641.73,4425.2) 6641.73,4354.33 6649.61,4346.46 R11.2@6677.17,4346.46 R10.1@6677.17,4314.96
  L1-TOP w6: MC3.48@2720.08,2332.68 2773.62,2332.68 v1(2842.52,2401.57)
  L8-SIG w5: v1(5933.07,4153.54) 6181.1,4401.57 6452.76,4401.57 6492.13,4440.94 6625.98,4440.94 v1(6641.73,4425.2)
  L10-BOT w5: v1(2842.52,2401.57) 2948.82,2507.87 4802.35,2507.87 5025.45,2730.97 5025.45,3311.8 5853.8,4140.16 5919.68,4140.16 v1(5933.07,4153.54)
NetR2_1: R2.1 R5.2 U1.1 | length 142.7
  L1-TOP w5: U1.1@7969.36,4906 8063.97,4906 8071.31,4898.66 R2.1@8071.31,4897 R5.2@8071.31,4861
NetR3_1: R3.1 R6.2 U1.2 | length 146.2
  L1-TOP w5: U1.2@7969.36,4956 8026.87,4956 8046.87,4976 R3.1@8071.31,4976 R6.2@8071.31,4940
NetR4_1: R4.1 R7.2 U1.3 | length 144.9
  L1-TOP w5: U1.3@7969.36,5006 8057.31,5006 8062,5010.69 8063.97,5010.69 8071.31,5018.03 R7.2@8071.31,5020 R4.1@8071.31,5056
NetR12_1: R12.1 U12.3 U13.17 | length 893.6
  L1-TOP w5: U12.3@5631.89,5482.28 5631.89,5458.66 5645.67,5444.88 5763.3,5444.88 5790.86,5472.44 5838.58,5472.44 5857.99,5453.04 5857.99,5151.2 5948.89,5060.29 5948.89,4988.26 5948.82,4988.19 ; U13.17@5902.45,4943.87 5902.45,4964.57 5926.07,4988.19 5948.82,4988.19 ; R12.1@5988.19,4988.19 5948.82,4988.19
NetR20_2: R20.2 U4.5 | length 77.7
  L1-TOP w8: U4.5@8125.61,3949.42 8125.61,3924.73 8123.54,3922.67 8123.54,3900.43 8127.72,3896.26 8127.72,3895.54 8141.35,3881.91 R20.2@8143.32,3881.91
NetR58_1: R58.1 R59.2 U16.6 | length 177.4
  L1-TOP w8: R58.1@4143.93,5570.09 4127.2,5570.09 4120.08,5577.21 R59.2@4120.08,5613.78 4143.7,5613.78 4155.51,5601.97 4194.88,5601.97 4200.79,5607.87 U16.6@4200.79,5633.86
NetR60_1: R60.1 R61.2 U17.6 | length 167.1
  L1-TOP w8: R61.2@4466.54,5613.78 4466.54,5596.06 4490.16,5572.44 R60.1@4490.16,5570.47 ; R61.2@4466.54,5614.17 4484.43,5614.17 4496.24,5602.36 4541.34,5602.36 4547.24,5608.27 U17.6@4547.24,5634.25
NetR66_2: R66.2 U12.5 | length 54.8
  L1-TOP w5: R66.2@5665.35,5330.71 5669.29,5334.65 U12.5@5669.29,5383.86
NetR67_1: R67.1 R68.1 R70.1 U13.23 | length 521.1
  L1-TOP w5: R67.1@5583.31,5331 R68.1@5583.31,5294 R70.1@5583.31,5257 5583.31,5180.46 5625.98,5137.8 5712.6,5137.8 5774.61,5075.79 5774.61,4974.89 5784.34,4965.15 U13.23@5784.34,4943.87
NetR67_2: R67.2 U14.27 | length 784.1
  L1-TOP w5: v1(5901.57,5547.24) 5902,5546.82 5902,5520.24 5887,5505.24 5887,5347 5905.41,5328.59 5983.41,5328.59 5993.01,5318.99 U14.27@6005.76,5318.99
  L8-SIG w5: v1(5622.69,5331) 5622.69,5465.2 5683.48,5526 5770.09,5526 5791.34,5547.24 v1(5901.57,5547.24)
NetR69_2: R69.2 U13.22 | length 48.4
  L1-TOP w7: R69.2@5800.02,4990.59 5804.02,4986.58 U13.22@5804.02,4943.87
NetR71_1: R71.1 R73.1 U14.3 | length 140.8
  L1-TOP w5: R73.1@5954.41,5188.01 R71.1@5990.41,5188.01 6014.4,5212 6033,5212 6053.01,5232.01 U14.3@6053.01,5256
NetR72_1: R72.1 U14.5 | length 77.1
  L1-TOP w5: R72.1@6062.41,5188.01 6062.41,5204.41 6084.5,5226.5 U14.5@6084.5,5256
NetR74_1: R74.1 U14.4 | length 85.5
  L1-TOP w5: R74.1@6026.41,5188.01 6068.76,5230.35 U14.4@6068.76,5256
NetR76_2: R76.2 U13.24 | length 52.1
  L1-TOP w7: R76.2@5749.61,4989.72 5749.61,4970.67 5764.65,4955.62 U13.24@5764.65,4943.87
NetR81_1: R81.1 R83.2 U14.22 | length 140.1
  L1-TOP w5: R81.1@5967.41,5414.64 R83.2@6003.41,5414.64 6022.22,5395.83 6044.17,5395.83 6068.76,5371.24 U14.22@6068.76,5350.49
NetR82_1: R82.1 U14.11 | length 37.7
  L1-TOP w5: U14.11@6178.99,5271.75 6215.83,5271.75 R82.1@6216.41,5272.32
NetR84_1: R84.1 R87.2 U15.1 | length 142.7
  L1-TOP w5: U15.1@7969.36,5154 8063.97,5154 8071.31,5146.66 R84.1@8071.31,5145 R87.2@8071.31,5109
NetR85_1: R85.1 R88.2 U15.2 | length 146.2
  L1-TOP w5: U15.2@7969.36,5204 8026.83,5204 8046.83,5224 R85.1@8071.31,5224 R88.2@8071.31,5188
NetR86_1: R86.1 R89.2 U15.3 | length 144.9
  L1-TOP w5: U15.3@7969.36,5254 8057.31,5254 8062,5258.69 8063.97,5258.69 8071.31,5266.03 R89.2@8071.31,5268 R86.1@8071.31,5304
NetR97_2: R97.2 U18.25 | length 157.5
  L1-TOP w6: R97.2@4362.2,5358.27 4360.24,5358.27 4338.58,5336.61 4338.58,5273.7 4359.9,5252.38 4359.9,5224.59 U18.25@4362.8,5221.69
NetR99_1: R99.1 U18.27 | length 137.8
  L1-TOP w6: U18.27@4323.17,5221.95 4323.17,5354.66 R99.1@4326.77,5358.27
NetR100_1: R100.1 U18.28 | length 169.8
  L1-TOP w6: R100.1@4285.71,5383.29 4285.71,5381.32 4303.75,5363.28 U18.28@4303.75,5221.69 U18.28@4303.26,5222.18
NetR101_1: R101.1 U18.24 | length 75.3
  L1-TOP w6: R101.1@4362.2,5287.4 4364.17,5287.4 4370.02,5281.56 4370.02,5275 4382.49,5262.53 U18.24@4382.49,5221.69
NetR111_1: R111.1 U18.18 | length 66.5
  L1-TOP w7: U18.18@4500.6,5221.69 4500.6,5279.58 R111.1@4506.66,5285.64
NetR118_2: R118.2 U18.15 | length 90.9
  L1-TOP w8: U18.15@4597.06,5125.23 4644.92,5125.23 4653.54,5133.86 4661.42,5141.73 R118.2@4661.42,5161.42
NetR131_1: R131.1 U19.38 | length 73.7
  L1-TOP w7: U19.38@1258,3695.75 1258,3650.5 1268.98,3639.52 1268.98,3637.55 1275.32,3631.21 R131.1@1277.29,3631.21
NetR136_1: R136.1 R137.1 U16.3 U17.3 | length 6676.5
  L1-TOP w5: R136.1@1499.46,4280 1499.46,4240.54 1518,4222 v1(1518,4199.69) ; v1(4193.36,5741.62) 4193.36,5740.2 4200.79,5732.78 U16.3@4200.79,5711.81 ; v1(4539.82,5741.62) 4539.82,5740.2 4547.24,5732.78 U17.3@4547.24,5711.81
  L8-SIG w5: v1(2779.53,5708.66) 2792.2,5695.99 3564.81,5695.99 3750.72,5881.89 3956.69,5881.89 4096.97,5741.62 v1(4193.36,5741.62) 4214.51,5720.47 4464.57,5720.47 4485.71,5741.62 v1(4539.82,5741.62)
  L10-BOT w5: v1(1518,4199.69) 1687.31,4199.69 1895,3992 1895,3619 2170,3344 2917.32,3344 ; v1(2779.53,5708.66) 2779.53,5685.04 2597.91,5503.43 2597.91,4720.98 2818.01,4500.89 2818.01,4280.91 2984.25,4114.67 2984.25,3410.93 2917.32,3344 ; 2922,3344 2917.32,3344
NetR136_2: R136.2 U19.17 | length 356
  L1-TOP w5: U19.17@1376.11,3959.53 1378.84,3962.25 1378.84,3987.08 v1(1381.32,3989.56)
  L10-BOT w5: v1(1381.32,3989.56) 1380.29,3989.56 1367.37,4002.48 1367.37,4214.84 v1(1432.54,4280)
NetR151_2: R151.2 R152.2 U34.5 | length 149.4
  L1-TOP w5: R152.2@2307.09,1063.39 R151.2@2271.65,1063.39 2271.65,1019.69 2298.82,992.52 U34.5@2330.71,992.52
NetR153_1: R153.1 R158.2 R168.1 R169.2 | length 297.1
  L1-TOP w6: R158.2@1660.84,1035 1657.84,1038 R168.1@1628.21,1038 R169.2@1628.21,1075 1628.21,1076.97 1664.2,1112.96 1749.96,1112.96 1773.21,1089.71 R153.1@1773.21,1035
NetU2_1: U2.1 Y2.3 | length 155.8
  L1-TOP w5: Y2.3@4387.4,574.8 4393.31,574.8 4427.17,608.66 U2.1@4427.17,710.63
NetU2_2: U2.2 Y2.1 | length 84.5
  L1-TOP w5: U2.2@4446.85,710.63 4446.85,658.92 4467.97,637.8 Y2.1@4470.87,637.8
PGOOD: Q1.1 R148.1 TP23.1 U16.5 U17.5 | length 5487.2
  L1-TOP w5: v1(944.88,5531.5) 944.88,5433.07 1106,5271.95 1106,4898 1061,4853 1061,4784 994,4717 994,4451 1014,4431 R148.1@1048.31,4431 ; Q1.1@1028.3,4477.3 1048.31,4457.28 R148.1@1048.31,4431 ; TP23.1@1224,4477 1224,4421 1204,4401 1057,4401 1048.31,4409.69 R148.1@1048.31,4431 ; v1(4157.99,5633.86) U16.5@4181.1,5633.86 U16.5@4181.36,5634.11 ; v1(4504.19,5633.6) 4527.31,5633.6 U17.5@4527.56,5633.86
  L8-SIG w5: v1(944.88,5531.5) 1161.42,5531.5 1181.1,5551.18 1602.36,5551.18 1625.98,5527.56 2574.8,5527.56 2731.03,5683.79 3573.27,5683.79 3755.62,5866.14 3948.82,5866.14 4066.93,5748.03 4066.93,5661.42 4094.49,5633.86 v1(4157.99,5633.86) 4158.11,5633.73 4504.06,5633.73 v1(4504.19,5633.6)
POR_OVERRIDE: J3.39 MC1.111 | length 1806.8
  L1-TOP w4.84: J3.39@3503.94,5000 3505.91,4998.03 3655.51,4998.03 v1(3657.48,4996.06)
  L10-BOT w4.84: v1(3657.48,4996.06) 3657.48,4285.52 3766,4177 3913.22,4177 4000,4263.78 4217.78,4263.78 4241,4287 4241,4411 4261.81,4431.81 v1(4261.81,4545.42)
PS_B500_MIO0: J3.23 MC1.79 | length 1320.3
  L1-TOP w4.55: J3.23@2874.02,5000 3047.02,4827 3708.17,4827 3946.85,4588.32 MC1.79@3946.85,4511.42
PS_B500_MIO1: J3.13 MC1.88 | length 2033.4
  L1-TOP w4.55: J3.13@2480.31,5000 2759.84,4720.47 3563.53,4720.47 3716,4568 3716,4483 3754,4445 4035,4445 4057,4423 4057,4349 4025.59,4317.59 MC1.88@4025.59,4268.11
PS_B500_MIO2: J3.11 MC1.86 | length 2091.8
  L1-TOP w4.55: J3.11@2401.57,5000 2704.72,4696.85 3556.15,4696.85 3693,4560 3693,4483 3744,4432 4023,4432 4046,4409 4046,4358 4005.91,4317.91 MC1.86@4005.91,4268.11
PS_B500_MIO4: J3.3 MC1.78 | length 2175.8
  L1-TOP w4.55: J3.3@2086.61,5000 2475.69,4610.92 2710.08,4610.92 2902.26,4418.74 2984.44,4418.74 3039.51,4363.67 3481.33,4363.67 3510,4335 3915,4335 3927.17,4322.83 MC1.78@3927.17,4268.11
PS_B500_MIO5: J3.15 MC1.90 | length 1980.8
  L1-TOP w4.55: J3.15@2559.06,5000 2818.9,4740.16 3578.74,4740.16 3732.22,4586.68 3732.22,4488.78 3762,4459 4044,4459 4073,4430 4073,4341 4045.28,4313.28 MC1.90@4045.28,4268.11
PS_B500_MIO7: J3.7 MC1.82 | length 2096.4
  L1-TOP w4.55: J3.7@2244.09,5000 2590.55,4653.54 2790.46,4653.54 3010.93,4433.07 3157.48,4433.07 3163.17,4427.38 3224.77,4427.38 3230.03,4432.64 3512.36,4432.64 3534,4411 3534,4371 3542,4363 3945,4363 3966.54,4341.46 MC1.82@3966.54,4268.11
PS_B500_MIO8: J3.33 MC1.89 | length 1050.5
  L1-TOP w4.55: J3.33@3267.72,5000 3330.72,4937 3740.17,4937 4045.28,4631.89 MC1.89@4045.28,4511.42
PS_B500_MIO11: J3.31 MC1.87 | length 1105.9
  L1-TOP w4.55: J3.31@3188.98,5000 3271.98,4917 3734.17,4917 4025.59,4625.58 MC1.87@4025.59,4511.42
PS_B500_MIO12: J3.21 MC1.77 | length 1372.1
  L1-TOP w4.55: J3.21@2795.28,5000 2990.28,4805 3698.17,4805 3927.16,4576 MC1.77@3927.16,4511.42
PS_B500_MIO13: J3.27 MC1.83 | length 1212.5
  L1-TOP w4.55: J3.27@3031.5,5000 3160.5,4871 3721.17,4871 3986.22,4605.95 MC1.83@3986.22,4511.42
PS_B500_MIO19: J3.1 MC1.76 | length 2222.3
  L1-TOP w4.55: J3.1@2007.87,5000 2157.94,4849.94 2187.06,4849.94 2447.08,4589.92 2659.08,4589.92 2899.8,4349.2 3458.8,4349.2 3487,4321 3888,4321 3907.48,4301.52 MC1.76@3907.48,4268.11
PS_B500_MIO20: J3.25 MC1.81 | length 1266.1
  L1-TOP w4.55: J3.25@2952.76,5000 3101.76,4851 3712.17,4851 3966.54,4596.63 MC1.81@3966.54,4511.42
PS_B500_MIO21: J3.19 MC1.75 | length 1422.2
  L1-TOP w4.55: J3.19@2716.54,5000 2935.54,4781 3687.17,4781 3907.48,4560.69 MC1.75@3907.48,4511.42
PS_B500_MIO22: J3.29 MC1.85 | length 1160
  L1-TOP w4.55: J3.29@3110.24,5000 3215.24,4895 3728.17,4895 4005.91,4617.26 MC1.85@4005.91,4511.42
PS_B500_MIO23: J3.17 MC1.73 | length 1475.8
  L1-TOP w4.55: J3.17@2637.8,5000 2878.8,4759 3680.17,4759 3887.79,4551.37 MC1.73@3887.79,4511.42
PS_B500_MIO24: J3.9 MC1.84 | length 2160.9
  L1-TOP w4.55: J3.9@2322.83,5000 2645.67,4677.17 3547.83,4677.17 3674,4551 3674,4472 3729,4417 4024,4417 4033,4408 4033,4369 3986.22,4322.22 MC1.84@3986.22,4268.11
PS_B500_MIO25: J3.5 MC1.80 | length 2144.4
  L1-TOP w4.55: J3.5@2165.35,5000 2535.43,4629.92 2790.25,4629.92 3009.34,4410.83 3506.17,4410.83 3511,4406 3511,4369 3530,4350 3599,4350 3930,4350 3946.85,4333.15 MC1.80@3946.85,4268.11
PS_DONE: J4.9 MC1.109 | length 3900.2
  L1-TOP w5: MC1.109@4242.13,4511.42 4242.13,4475.17 4295.28,4422.02 4295.28,4370.08 4338.58,4326.77 4467.64,4326.77 4668.43,4125.98 5642.34,4125.98 6227.74,4711.38 6227.74,4931.93 6644.81,5349 7120.65,5349 J4.9@7244.09,5472.44
PS_ERROR_OUT: J4.3 MC1.117 | length 3504.1
  L1-TOP w4.84: MC1.117@4320.87,4511.42 4320.87,4478.13 4361.99,4437.01 4476.75,4437.01 4728.72,4185.04 5617.88,4185.04 6168.69,4735.85 6168.69,4956.4 6625.68,5413.39 6948.82,5413.39 J4.3@7007.87,5472.44
PS_ERROR_STATUS: J4.5 MC1.115 | length 3620.8
  L1-TOP w4.84: MC1.115@4301.18,4511.42 4301.18,4474.82 4358.68,4417.32 4456.43,4417.32 4708.4,4165.35 5626.03,4165.35 6188.37,4727.69 6188.37,4948.24 6632.13,5392 7006.17,5392 J4.5@7086.61,5472.44
PS_I2C0_SCL_3V3: J1.1@3488.28,5821.46 J5.1@7119.64,83.86 J6.1@3025.15,83.86 J7.1@5072.39,83.86 J8.1@84.05,1598.51 J9.1@84.05,3448.91 J11.1@1637.88,5821.46 J13.3 MC1.58 U1.6 U2.12 U14.26 U15.6 U19.43 | length 26665.9
  L1-TOP w5: J8.1@84.05,1598.51 120.49,1598.51 173,1546 198,1546 218,1526 218,906 444,680 444,232 628,48 2937.76,48 2968.5,78.74 v1(2984.25,78.74) 3022.14,78.74 3025.15,81.75 J6.1@3025.15,83.86 J6.1@3025.15,123.85 ; J9.1@84.05,3448.91 122.77,3448.91 141.54,3467.67 v1(144.89,3467.67) 174,3438.56 174,3407 184,3397 208,3397 240,3365 240,2713 374,2579 374,1888 169,1683 169,1646 J8.1@123.98,1600.98 ; U19.43@1356.43,3695.75 1356.43,3685.57 1372.55,3669.45 v1@1372.55,3666.81 ; J11.1@1637.88,5821.46 1637.88,5787.12 1649,5776 1666,5776 v1(1680,5790) ; J1.1@3488.28,5821.46 3488.28,5800.78 3493.78,5795.28 v1(3531.5,5795.28) ; MC1.58@3533.46,4268.11 3533.46,4301.18 3539.37,4307.09 3574.8,4307.09 3618.11,4263.78 v1(3618.11,4248.03) ; U2.12@4553.15,836.61 4563.98,836.61 4578.07,850.7 4578.07,861.53 v1(4578.74,862.2) ; v1(5934.01,5349.93) 5985.07,5349.93 6000.26,5334.74 U14.26@6005.76,5334.74 ; v1(7070.87,66.93) 7087.8,83.86 J5.1@7119.64,83.86 ; v1(7704,5253) 7705,5254 U15.6@7764.64,5254
  L1-TOP w6: v1(7704,5005) 7705,5006 7848.33,5006 7897.64,4956.69 7897.64,4854.33 7975.59,4776.38 J13.3@7975.59,4704.72
  L1-TOP w11: v1@1372.55,3666.81 v1(1373.14,3666.81)
  L8-SIG w5: v1(144.89,3467.67) 144.89,3510.89 162,3528 222,3528 258,3492 1120,3492 1254,3626 1332.33,3626 v1(1373.14,3666.81) ; v1(1680,5790) 1745,5855 2682,5855 2731.32,5805.68 2908.04,5805.68 2925.2,5822.83 3503.94,5822.83 v1(3531.5,5795.28)
  L3-PWR w5: v1(1373.14,3666.81) 1393.03,3666.81 1452.76,3726.53 1452.76,4027.56 1429.13,4051.18 1429.13,4074.8 1327.39,4176.54 1230.92,4176.54 1219.72,4187.75 1219.72,4220.28 854,4586 854,5666 895,5707 895,5796.04 917.96,5819 1651,5819 v1(1680,5790) ; v1(2984.25,78.74) 2986.74,81.23 2992.9,81.23 2993.68,82.01 5025.3,82.01 v1@5067.9,39.41 ; v1(5067.35,38.86) v1@5067.9,39.41 ; v1(7070.87,66.93) 7051.18,66.93 7043.31,59.06 5688.98,59.06 5665.35,82.68 5111.17,82.68 v1@5067.9,39.41
  L10-BOT w5: v1(3531.5,5795.28) 3717.17,5609.6 3717.17,5106.15 3624.7,5013.68 3624.7,4286.11 3618.11,4279.53 v1(3618.11,4248.03) 3618.11,4208.66 3685.04,4141.73 5606.69,4141.73 6035.78,4570.82 6035.78,4983.57 5900.55,5118.8 5900.55,5316.48 v1(5934.01,5349.93) 5934.01,5371.44 5956.57,5394 5974,5394 6002.97,5365.03 6064.11,5365.03 6156.74,5272.39 6224.62,5272.39 6243.57,5291.34 6319.34,5291.34 6349.24,5321.24 7713.76,5321.24 7730,5305 7730,5279 v1(7704,5253) 7745,5212 7745,5046 v1(7704,5005) ; v1(4578.74,862.2) 4578.74,543.31 5067.35,54.69 v1(5067.35,38.86)
PS_I2C0_SDA_3V3: J1.3 J5.3 J6.3 J7.3 J8.3 J9.3 J11.3 J13.2 MC1.60 U1.5 U2.19 U14.25 U15.5 U19.42 | length 27281
  L1-TOP w5: J9.3@84.05,3417.41 145.65,3417.41 v1(155.2,3426.95) 155.2,3424.22 165.5,3413.92 165.5,3403.48 186.42,3382.56 199.09,3382.56 220,3361.65 220,2701 352,2569 352,1896 176,1720 123,1720 22,1619 22,1590.83 45.82,1567.01 J8.3@84.05,1567.01 120.99,1567.01 130,1558 141,1558 174,1525 174,912 417,669 417,229 615,31 2942,31 2962.18,51.18 v1(2984.25,51.18) 3007.62,27.81 3032.34,27.81 3041.82,37.29 3041.82,80.85 J6.3@3044.83,83.86 ; U19.42@1336.74,3695.75 1336.74,3688.26 1342.54,3682.46 v1@1342.54,3666.9 ; J11.3@1606.38,5821.46 1606.38,5854.75 1630.63,5879 1670,5879 v1(1679,5870) ; J1.3@3456.78,5821.46 3456.78,5784.71 3477.71,5763.78 v1(3531.5,5763.78) ; MC1.60@3553.15,4268.11 3553.15,4245.47 3556.55,4242.07 3566.14,4232.48 v1@3586.42,4232.48 ; v1(4374.02,862.2) 4374.69,861.53 4374.69,850.7 4388.78,836.61 U2.19@4399.61,836.61 ; v1(5963.27,5373.14) 6004.86,5373.14 6021.51,5356.49 U14.25@6021.51,5350.49 ; v1(7070.87,39.37) 7082.68,27.56 7133.86,27.56 7139.32,33.02 J5.3@7139.32,83.86 ; v1(7705,5055) 7706,5056 U1.5@7764.64,5056 ; v1(7705,5303) 7706,5304 U15.5@7764.64,5304
  L1-TOP w6: v1(7705,5055) 7673.23,5023.23 7673.23,5000 7692.91,4980.31 7834.65,4980.31 7875.59,4939.37 J13.2@7875.59,4704.72
  L1-TOP w11: v1@1342.54,3666.9 v1(1343.13,3666.9)
  L8-SIG w5: v1(155.2,3426.95) 141.45,3426.95 124,3444.4 124,3515 154,3545 235,3545 271,3509 1085,3509 1216,3640 1316.23,3640 v1(1343.13,3666.9) ; v1(1679,5870) 2698,5870 2731.76,5836.24 3522.03,5836.24 3555.12,5803.15 3555.12,5787.4 v1(3531.5,5763.78)
  L3-PWR w5: v1(1343.13,3666.9) 1365.2,3688.98 1393.7,3688.98 1437.01,3732.28 1437.01,3985.02 1405.47,4016.56 1405.47,4039.41 1362.53,4082.35 1362.53,4122.66 1320.47,4164.73 1226.98,4164.73 1207.91,4183.81 1207.91,4212.57 838.34,4582.14 838.34,5657.81 819.2,5676.95 819.2,5755.2 905,5841 1650,5841 v1(1679,5870) ; v1(2984.25,51.18) 3007.87,51.18 3026.67,69.98 5007.06,69.98 5054.3,22.74 5080.99,22.74 5129.12,70.87 5658.72,70.87 5682.34,47.24 7046.73,47.24 7054.6,39.37 v1(7070.87,39.37)
  L10-BOT w5: v1(3531.5,5763.78) 3543.31,5763.78 3702.7,5604.39 3702.7,5112.15 3608.96,5018.41 3608.96,4297.94 3586.61,4275.59 v1(3586.61,4232.28) 3586.61,4216.54 3673.15,4130 5614.47,4130 6050.05,4565.58 6050.05,4986.07 5913,5123.12 5913,5301.33 5952.58,5340.91 5952.58,5362.44 v1(5963.27,5373.14) 5963.73,5372.68 5974.77,5372.68 5998.53,5348.92 6009.35,5348.92 6097.44,5260.83 6235.59,5260.83 6245.56,5250.85 6305.83,5250.85 6357.98,5303 v1(7705,5303) 7669.29,5267.29 7669.29,5177.17 7705,5141.46 v1(7705,5055) ; v1(4374.02,862.2) 4535.43,862.2 4578.74,905.51 4614.17,905.51 4633.86,885.83 4633.86,527.56 5097.11,64.3 v1(5097.11,38.86)
PS_INIT_B: J4.19 MC1.112 | length 4234.8
  L1-TOP w4.84: MC1.112@4261.81,4268.11 4261.81,4214.33 4448.58,4027.56 5683.11,4027.56 6326.17,4670.62 6326.17,4891.17 6673,5238 7403.35,5238 J4.19@7637.8,5472.44
PS_JTAG_TCK: J2.6 MC1.59 U3.4 | length 7964.3
  L1-TOP w4.96: J2.6@8554.76,5245.74 8514.76,5205.74 8454.3,5205.74 8389.76,5141.2 8389.76,4600.98 8400.14,4590.61 8421.26,4590.61 8445.18,4590.61 cw(c8445.18,4584.62) 8451.17,4584.62 8451.17,4577.96 ccw(c8457.17,4577.96) 8457.17,4571.96 8475.14,4571.96 ccw(c8475.14,4577.96) 8481.14,4577.96 8481.14,4609.62 cw(c8487.13,4609.62) 8487.13,4615.61 8505.11,4615.61 cw(c8505.11,4609.62) 8511.1,4609.62 8511.1,4564.79 ccw(c8517.09,4564.79) 8517.09,4558.8 8535.07,4558.8 ccw(c8535.07,4564.79) 8541.06,4564.79 8541.06,4609.62 cw(c8547.06,4609.62) 8547.06,4615.61 8565.03,4615.61 cw(c8565.03,4609.62) 8571.03,4609.62 8571.03,4564.79 ccw(c8577.02,4564.79) 8577.02,4558.8 8595,4558.8 ccw(c8595,4564.79) 8600.99,4564.79 8600.99,4609.62 cw(c8606.98,4609.62) 8606.98,4615.61 8624.96,4615.61 cw(c8624.96,4609.62) 8630.95,4609.62 8630.95,4564.79 ccw(c8636.94,4564.79) 8636.94,4558.8 8654.92,4558.8 ccw(c8654.92,4564.79) 8660.91,4564.79 8660.91,4584.62 cw(c8666.91,4584.62) 8666.91,4590.61 8669.39,4590.61 8687.89,4590.61 8716.54,4561.96 8716.54,4118.11 8649.23,4050.8 U3.4@8582.3,4050.8
  L8-SIG w4.05: v1(3553.15,4477.42) 3571.5,4459.06 3759.25,4459.06 3809.11,4409.21 3809.11,4375.69 3834.48,4350.31 3887.79,4350.31 4094.1,4144 5002.27,4144 5027.56,4169.29 5141.73,4169.29 5143.76,4169.29 ccw(c5143.76,4174.1) 5148.57,4174.1 5148.57,4186.36 cw(c5153.38,4186.36) 5153.38,4191.17 5167.81,4191.17 cw(c5167.81,4186.36) 5172.62,4186.36 5172.62,4151.74 ccw(c5177.43,4151.74) 5177.43,4146.93 5191.86,4146.93 ccw(c5191.86,4151.74) 5196.67,4151.74 5196.67,4186.36 cw(c5201.48,4186.36) 5201.48,4191.17 5215.91,4191.17 cw(c5215.91,4186.36) 5220.72,4186.36 5220.72,4151.74 ccw(c5225.53,4151.74) 5225.53,4146.93 5239.96,4146.93 ccw(c5239.96,4151.74) 5244.77,4151.74 5244.77,4164.48 cw(c5249.58,4164.48) 5249.58,4169.29 5264.53,4169.29 5596.46,4169.29 6068.06,4640.89 6068.06,4910.48 6270.18,5112.6 7816.6,5112.6 7870,5166 8412.06,5166 8451.8,5205.74 8514.76,5205.74 J2.6@8554.76,5245.74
